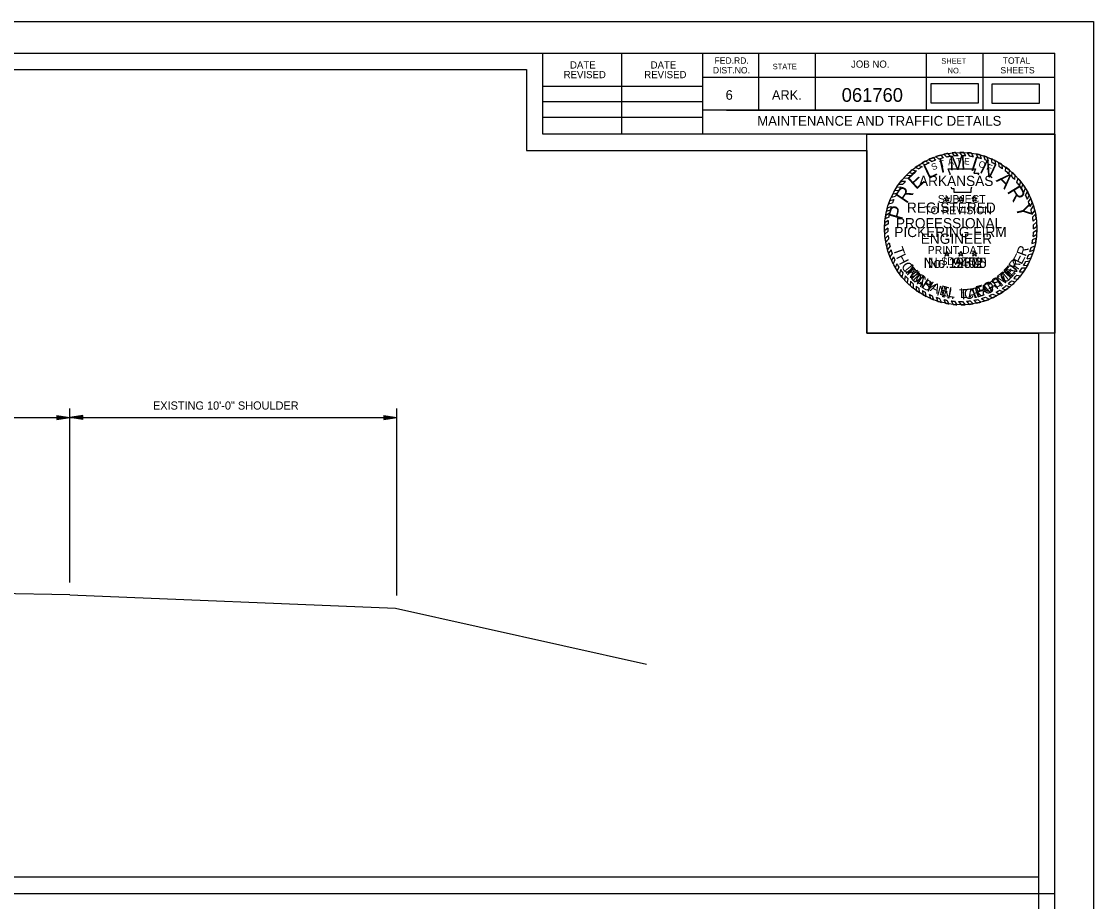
# Model space of a CAD drawing. Extents: x -500 to 213, y 382723 to 382830.
# Drawn here: x 147.8 to 213.4, y 382776 to 382829.8 of the extents above; entities that cross this region are included whole.
import ezdxf

# ---------------------------------------------------------------- set-up
doc = ezdxf.new("R2010")
doc.units = 0
for name, color, linetype in [('Default', 7, 'Continuous'), ('R_Border', 7, 'Continuous'), ('R_Border Notes', 7, 'Continuous'), ('R_Border Plan-Plan', 7, 'Continuous'), ('R_No Plot', 7, 'Continuous'), ('STAMP_PE_CRAFTON', 7, 'Continuous'), ('STAMP_PE_FOSTER', 7, 'Continuous'), ('STAMP_PE_SEAL-INFO', 7, 'Continuous'), ('STAMP_PE_TAEGTMEYER', 7, 'Continuous'), ('STAMP_PE_TXT', 7, 'Continuous'), ('STAMP_PRELIMINARY', 7, 'Continuous')]:
    doc.layers.add(name, color=color, linetype=linetype)

msp = doc.modelspace()

# ---------------------------------------------------------------- linework, layer by layer
at = {"layer": 'Default'}
for p, q in [((150.803, 382804.615), (150.803, 382806.125)), ((170.807, 382804.767), (170.807, 382806.125)), ((126.798, 382805.575), (150.803, 382805.575)), ((150.003, 382805.695), (150.803, 382805.575)), ((150.003, 382805.695), (150.003, 382805.455)), ((150.003, 382805.675), (150.669, 382805.575)), ((150.003, 382805.655), (150.531, 382805.575)), ((150.003, 382805.635), (150.399, 382805.575)), ((150.003, 382805.615), (150.263, 382805.575)), ((150.003, 382805.595), (150.129, 382805.575)), ((150.003, 382805.455), (150.803, 382805.575)), ((150.003, 382805.537), (150.263, 382805.575)), ((150.003, 382805.495), (150.531, 382805.575)), ((150.003, 382805.475), (150.669, 382805.575)), ((150.003, 382805.515), (150.399, 382805.575)), ((150.003, 382805.557), (150.129, 382805.575)), ((151.603, 382805.695), (150.803, 382805.575)), ((150.803, 382805.575), (170.807, 382805.575)), ((151.603, 382805.455), (150.803, 382805.575)), ((151.603, 382805.675), (150.937, 382805.575)), ((151.603, 382805.475), (150.937, 382805.575)), ((151.603, 382805.655), (151.075, 382805.575)), ((151.603, 382805.495), (151.075, 382805.575)), ((151.603, 382805.635), (151.207, 382805.575)), ((151.603, 382805.515), (151.207, 382805.575)), ((151.603, 382805.615), (151.343, 382805.575)), ((151.603, 382805.537), (151.343, 382805.575)), ((151.603, 382805.595), (151.477, 382805.575)), ((151.603, 382805.557), (151.477, 382805.575)), ((151.603, 382805.455), (151.603, 382805.695)), ((170.007, 382805.695), (170.807, 382805.575)), ((170.007, 382805.695), (170.007, 382805.455)), ((170.007, 382805.675), (170.673, 382805.575)), ((170.007, 382805.655), (170.535, 382805.575)), ((170.007, 382805.635), (170.403, 382805.575)), ((170.007, 382805.615), (170.267, 382805.575)), ((170.007, 382805.595), (170.133, 382805.575)), ((170.007, 382805.455), (170.807, 382805.575)), ((170.007, 382805.537), (170.267, 382805.575)), ((170.007, 382805.495), (170.535, 382805.575)), ((170.007, 382805.475), (170.673, 382805.575)), ((170.007, 382805.515), (170.403, 382805.575)), ((170.007, 382805.557), (170.133, 382805.575)), ((150.803, 382795.489), (150.803, 382804.615)), ((170.807, 382794.691), (170.807, 382804.767)), ((150.803, 382794.729), (126.798, 382795.209)), ((150.803, 382794.729), (170.731, 382793.933)), ((170.731, 382793.933), (186.09, 382790.492))]:
    msp.add_line(p, q, dxfattribs=at)
for points in [[(203.479, 382824.821), (206.395, 382824.821), (206.395, 382825.976), (203.479, 382825.976)], [(207.217, 382824.804), (210.134, 382824.804), (210.134, 382825.959), (207.217, 382825.959)]]:
    msp.add_lwpolyline(points, close=True, dxfattribs=at)
at = {"layer": 'R_Border'}
for p, q in [((52.967, 382827.85), (211.057, 382827.85)), ((179.737, 382822.91), (179.737, 382827.85)), ((184.577, 382822.91), (184.577, 382827.85)), ((189.507, 382827.85), (189.507, 382822.91)), ((192.927, 382827.85), (192.927, 382824.38)), ((196.397, 382827.85), (196.397, 382824.38)), ((203.187, 382827.85), (203.187, 382824.38)), ((206.657, 382827.85), (206.657, 382824.38)), ((211.057, 382725.12), (211.057, 382827.85)), ((211.057, 382826.38), (189.507, 382826.38)), ((211.057, 382826.39), (211.057, 382826.39)), ((179.737, 382825.84), (189.507, 382825.84)), ((179.737, 382824.91), (189.507, 382824.91)), ((211.057, 382824.38), (189.507, 382824.38)), ((190.987, 382824.38), (211.057, 382824.38)), ((179.737, 382823.94), (189.507, 382823.94)), ((211.057, 382822.91), (179.737, 382822.91))]:
    msp.add_line(p, q, dxfattribs=at)
at = {"layer": 'R_Border Plan-Plan'}
msp.add_line((52.967, 382776.485), (211.057, 382776.485), dxfattribs=at)
at = {"layer": 'R_No Plot'}
for points in [[(46.763, 382829.798), (213.433, 382829.798), (213.433, 382723.129), (46.763, 382723.129)], [(210.057, 382777.485), (53.967, 382777.485), (53.967, 382826.85), (178.737, 382826.85), (178.737, 382821.91), (187.507, 382821.91), (199.557, 382821.91), (199.557, 382810.744), (210.057, 382810.744)], [(53.967, 382826.85), (178.737, 382826.85), (178.737, 382821.91), (187.507, 382821.91), (199.557, 382821.91), (199.557, 382810.744), (210.057, 382810.744), (210.057, 382726.12), (53.967, 382726.12)], [(199.557, 382822.91), (211.057, 382822.91), (211.057, 382810.744), (199.557, 382810.744)]]:
    msp.add_lwpolyline(points, close=True, dxfattribs=at)
at = {"layer": 'STAMP_PE_SEAL-INFO'}
for p, q in [((204.082, 382821.629), (204.226, 382821.455)), ((204.276, 382821.678), (204.454, 382821.506)), ((204.517, 382821.726), (204.667, 382821.542)), ((204.775, 382821.763), (204.915, 382821.571)), ((205.143, 382821.585), (204.987, 382821.782)), ((205.392, 382821.588), (205.252, 382821.793)), ((205.621, 382821.577), (205.491, 382821.789)), ((205.873, 382821.552), (205.727, 382821.774)), ((206.086, 382821.52), (205.958, 382821.747)), ((206.367, 382821.46), (206.28, 382821.69)), ((206.568, 382821.406), (206.489, 382821.641)), ((206.794, 382821.333), (206.723, 382821.573)), ((202.726, 382821.013), (202.947, 382820.912)), ((202.919, 382821.135), (203.135, 382821.024)), ((203.143, 382821.261), (203.375, 382821.148)), ((203.359, 382821.366), (203.553, 382821.229)), ((203.613, 382821.474), (203.76, 382821.311)), ((203.786, 382821.538), (203.977, 382821.385)), ((207.003, 382821.253), (206.931, 382821.501)), ((207.234, 382821.15), (207.183, 382821.399)), ((207.457, 382821.036), (207.413, 382821.29)), ((207.651, 382820.922), (207.631, 382821.172)), ((207.868, 382820.779), (207.852, 382821.037)), ((201.988, 382820.405), (202.26, 382820.384)), ((202.155, 382820.566), (202.385, 382820.497)), ((202.327, 382820.716), (202.592, 382820.666)), ((202.516, 382820.88), (202.743, 382820.778)), ((204.543, 382820.777), (206.215, 382820.777)), ((204.604, 382820.624), (204.543, 382820.777)), ((204.656, 382820.475), (204.604, 382820.624)), ((204.659, 382820.418), (204.656, 382820.475)), ((206.215, 382820.777), (206.103, 382820.531)), ((206.103, 382820.531), (206.419, 382820.531)), ((206.419, 382820.531), (206.347, 382820.418)), ((208.048, 382820.646), (208.065, 382820.889)), ((208.271, 382820.459), (208.281, 382820.721)), ((208.428, 382820.313), (208.462, 382820.563)), ((208.607, 382820.127), (208.641, 382820.39)), ((201.397, 382819.67), (201.655, 382819.687)), ((201.514, 382819.842), (201.767, 382819.839)), ((201.653, 382820.027), (201.928, 382820.038)), ((201.826, 382820.232), (202.087, 382820.213)), ((204.755, 382819.563), (204.742, 382819.672)), ((205.974, 382819.672), (205.935, 382819.517)), ((208.744, 382819.968), (208.812, 382820.204)), ((208.906, 382819.76), (208.974, 382820.01)), ((209.016, 382819.602), (209.105, 382819.834)), ((209.17, 382819.354), (209.261, 382819.599)), ((201.064, 382819.063), (201.316, 382819.115)), ((201.158, 382819.258), (201.408, 382819.29)), ((201.274, 382819.469), (201.519, 382819.48)), ((204.912, 382819.563), (204.755, 382819.563)), ((204.912, 382819.348), (204.912, 382819.563)), ((205.927, 382819.348), (204.912, 382819.348)), ((205.935, 382819.517), (205.927, 382819.348)), ((209.27, 382819.17), (209.383, 382819.392)), ((209.385, 382818.928), (209.498, 382819.171)), ((209.456, 382818.76), (209.587, 382818.977)), ((200.767, 382818.189), (201.002, 382818.285)), ((200.819, 382818.393), (201.058, 382818.477)), ((200.897, 382818.644), (201.14, 382818.712)), ((200.972, 382818.847), (201.225, 382818.92)), ((209.553, 382818.485), (209.688, 382818.722)), ((209.607, 382818.303), (209.754, 382818.529)), ((200.906, 382817.836), (200.683, 382817.725)), ((200.949, 382818.066), (200.716, 382817.941)), ((209.673, 382818.024), (209.833, 382818.247)), ((209.708, 382817.834), (209.885, 382818.01)), ((209.741, 382817.579), (209.927, 382817.747)), ((200.858, 382817.406), (200.648, 382817.278)), ((200.85, 382817.159), (200.648, 382816.991)), ((200.877, 382817.618), (200.658, 382817.478)), ((209.757, 382817.37), (209.952, 382817.516)), ((209.758, 382816.908), (209.967, 382817.047)), ((209.763, 382817.111), (209.966, 382817.272)), ((200.853, 382816.956), (200.658, 382816.793)), ((200.87, 382816.708), (200.684, 382816.53)), ((200.896, 382816.493), (200.719, 382816.307)), ((209.713, 382816.461), (209.934, 382816.571)), ((209.738, 382816.655), (209.955, 382816.783)), ((200.935, 382816.264), (200.766, 382816.08)), ((200.982, 382816.055), (200.826, 382815.847)), ((201.044, 382815.831), (200.897, 382815.622)), ((209.54, 382815.738), (209.785, 382815.838)), ((209.613, 382815.985), (209.849, 382816.086)), ((209.667, 382816.211), (209.895, 382816.309)), ((201.114, 382815.619), (200.974, 382815.414)), ((201.198, 382815.406), (201.067, 382815.195)), ((201.283, 382815.214), (201.17, 382814.984)), ((209.285, 382815.123), (209.529, 382815.157)), ((209.366, 382815.291), (209.61, 382815.339)), ((209.473, 382815.548), (209.714, 382815.614)), ((201.401, 382814.985), (201.305, 382814.74)), ((201.519, 382814.784), (201.427, 382814.548)), ((201.62, 382814.628), (201.565, 382814.352)), ((201.76, 382814.433), (201.709, 382814.167)), ((208.893, 382814.486), (209.146, 382814.488)), ((209.063, 382814.733), (209.302, 382814.73)), ((209.149, 382814.873), (209.399, 382814.901)), ((201.912, 382814.244), (201.869, 382813.984)), ((202.064, 382814.075), (202.033, 382813.814)), ((202.225, 382813.912), (202.21, 382813.648)), ((202.397, 382813.756), (202.395, 382813.491)), ((208.217, 382813.757), (208.453, 382813.692)), ((208.42, 382813.943), (208.641, 382813.874)), ((208.548, 382814.073), (208.786, 382814.03)), ((208.739, 382814.289), (208.97, 382814.249)), ((202.577, 382813.609), (202.586, 382813.347)), ((202.746, 382813.484), (202.764, 382813.225)), ((202.96, 382813.343), (202.99, 382813.087)), ((203.135, 382813.24), (203.18, 382812.984)), ((203.375, 382813.115), (203.454, 382812.855)), ((207.269, 382813.13), (207.511, 382813.024)), ((207.473, 382813.237), (207.681, 382813.12)), ((207.68, 382813.359), (207.905, 382813.261)), ((207.852, 382813.473), (208.071, 382813.378)), ((208.082, 382813.645), (208.316, 382813.572)), ((203.562, 382813.031), (203.648, 382812.775)), ((203.808, 382812.935), (203.913, 382812.684)), ((204.013, 382812.867), (204.126, 382812.622)), ((204.267, 382812.798), (204.373, 382812.565)), ((204.465, 382812.755), (204.589, 382812.526)), ((204.716, 382812.714), (204.836, 382812.494)), ((204.934, 382812.691), (205.071, 382812.476)), ((205.176, 382812.677), (205.327, 382812.47)), ((205.406, 382812.676), (205.578, 382812.478)), ((205.665, 382812.689), (205.828, 382812.5)), ((205.884, 382812.713), (206.071, 382812.533)), ((206.107, 382812.747), (206.301, 382812.578)), ((206.353, 382812.8), (206.542, 382812.637)), ((206.583, 382812.862), (206.791, 382812.713)), ((206.829, 382812.943), (207.051, 382812.809)), ((207.039, 382813.025), (207.251, 382812.895))]:
    msp.add_line(p, q, dxfattribs=at)
for radius, start, end in [(4.661, 105.23389, 109.03519), (4.661, 99.75254, 102.77648), (4.661, 93.93815, 96.55172), (4.457, 92.11016, 95.03666), (4.661, 87.72979, 90.67067), (4.457, 85.96279, 88.9097), (4.661, 81.97315, 84.82355), (4.661, 75.31251, 77.94263), (4.661, 69.60611, 72.30577), (4.661, 123.61993, 126.59063), (4.457, 121.97456, 125.11001), (4.661, 117.65441, 120.80988), (4.457, 115.68692, 119.15827), (4.661, 111.31242, 114.70259), (4.457, 110.30864, 113.16588), (4.457, 104.03521, 107.36155), (4.457, 98.25799, 101.03289), (4.457, 79.92642, 82.69597), (4.457, 73.55748, 76.23144), (4.457, 67.62483, 70.50398), (4.661, 63.13288, 66.2704), (4.457, 61.15575, 64.37837), (4.661, 56.90029, 60.09423), (4.457, 54.92383, 58.27016), (4.661, 135.40208, 138.30314), (4.457, 133.13306, 136.25623), (4.661, 129.73259, 132.53764), (4.457, 127.52969, 130.96829), (4.457, 48.30163, 52.03953), (4.661, 50.3492, 53.71593), (4.457, 42.22116, 45.55119), (4.661, 44.3405, 47.39292), (4.661, 147.00719, 149.89904), (4.661, 141.60556, 144.44865), (4.457, 145.01972, 148.21036), (4.457, 139.30101, 142.58729), (4.457, 36.13503, 39.53106), (4.661, 38.12472, 41.23157), (4.457, 29.90321, 33.66454), (4.661, 31.96138, 35.42937), (4.661, 152.86398, 155.51889), (4.457, 151.03153, 153.57304), (4.457, 23.77322, 27.22114), (4.661, 25.93909, 29.01247), (4.661, 19.95381, 23.31409), (4.661, 164.3068, 166.89395), (4.661, 158.40766, 161.07015), (4.457, 162.43309, 165.00133), (4.457, 156.34018, 159.23194), (4.457, 17.68022, 21.42509), (4.457, 11.54445, 15.23639), (4.661, 13.84205, 17.44468), (4.661, 170.0003, 172.68778), (4.457, 167.90481, 170.90393), (4.457, 5.7599, 9.06056), (4.661, 7.58519, 10.86211), (4.661, 175.74093, 178.2066), (4.661, 181.72508, 184.16255), (4.457, 179.64537, 182.26333), (4.457, 173.73, 176.47337), (4.457, 359.73289, 3.06392), (4.661, 1.72155, 4.72681), (4.661, 355.71562, 358.95694), (4.661, 187.42037, 190.19271), (4.457, 185.45389, 188.23401), (4.457, 348.07782, 351.34355), (4.457, 353.86319, 357.12742), (4.661, 349.83047, 353.08845), (4.661, 193.03695, 195.99732), (4.457, 191.22736, 193.98583), (4.457, 196.96751, 199.83526), (4.457, 341.77699, 345.09248), (4.661, 343.89247, 347.03502), (4.661, 198.89671, 201.62812), (4.661, 204.54793, 207.43282), (4.457, 202.77613, 205.47915), (4.457, 329.55488, 333.20757), (4.457, 335.6038, 339.18578), (4.661, 331.40371, 334.93315), (4.661, 337.38367, 340.99332), (4.661, 210.86355, 213.65709), (4.457, 208.78826, 211.79343), (4.661, 216.61154, 219.49098), (4.457, 214.18375, 217.27474), (4.457, 323.58513, 327.44069), (4.661, 325.44052, 328.98725), (4.661, 222.47995, 225.38008), (4.457, 220.39088, 223.30564), (4.457, 226.24938, 229.24068), (4.457, 310.77436, 314.31605), (4.661, 312.45177, 315.66328), (4.457, 316.65308, 320.37109), (4.661, 318.28455, 321.80429), (4.661, 228.36648, 231.34802), (4.457, 232.22904, 234.93361), (4.661, 234.29502, 236.94517), (4.457, 238.22227, 240.83529), (4.661, 240.1977, 242.86128), (4.457, 244.32043, 246.94859), (4.457, 292.87452, 296.11851), (4.457, 299.07679, 302.17235), (4.661, 300.62101, 303.87026), (4.457, 304.82299, 308.51428), (4.661, 306.37206, 310.20799), (4.661, 246.57598, 249.15579), (4.457, 250.34912, 253.12157), (4.661, 252.59667, 255.32518), (4.457, 256.50505, 259.11916), (4.661, 258.44328, 261.13983), (4.457, 262.37828, 265.20115), (4.661, 264.19784, 267.10092), (4.457, 268.3215, 271.27698), (4.661, 270.25484, 273.33609), (4.457, 274.61565, 277.44863), (4.661, 276.42389, 279.43574), (4.457, 280.34588, 283.58137), (4.661, 282.31994, 285.37019), (4.457, 286.64233, 289.97826), (4.661, 288.57086, 291.97334), (4.661, 294.64808, 298.21662)]:
    msp.add_arc((205.307, 382817.132), radius, start, end, dxfattribs=at)
at = {"layer": 'STAMP_PE_TXT'}
for p, q in [((204.396, 382818.917), (204.297, 382818.99)), ((204.297, 382818.99), (204.42, 382818.99)), ((204.42, 382818.99), (204.458, 382819.106)), ((204.458, 382819.106), (204.496, 382818.99)), ((204.496, 382818.99), (204.618, 382818.99)), ((204.618, 382818.99), (204.519, 382818.917)), ((205.245, 382818.917), (205.146, 382818.99)), ((205.146, 382818.99), (205.269, 382818.99)), ((205.269, 382818.99), (205.307, 382819.106)), ((205.307, 382819.106), (205.345, 382818.99)), ((205.345, 382818.99), (205.467, 382818.99)), ((205.467, 382818.99), (205.368, 382818.917)), ((206.094, 382818.917), (205.995, 382818.99)), ((205.995, 382818.99), (206.118, 382818.99)), ((206.118, 382818.99), (206.156, 382819.106)), ((206.156, 382819.106), (206.194, 382818.99)), ((206.194, 382818.99), (206.316, 382818.99)), ((206.316, 382818.99), (206.217, 382818.917)), ((204.359, 382818.801), (204.396, 382818.917)), ((204.458, 382818.873), (204.359, 382818.801)), ((204.557, 382818.801), (204.458, 382818.873)), ((204.519, 382818.917), (204.557, 382818.801)), ((205.208, 382818.801), (205.245, 382818.917)), ((205.307, 382818.873), (205.208, 382818.801)), ((205.406, 382818.801), (205.307, 382818.873)), ((205.368, 382818.917), (205.406, 382818.801)), ((206.057, 382818.801), (206.094, 382818.917)), ((206.156, 382818.873), (206.057, 382818.801)), ((206.255, 382818.801), (206.156, 382818.873)), ((206.217, 382818.917), (206.255, 382818.801)), ((204.42, 382815.636), (204.458, 382815.753)), ((204.458, 382815.753), (204.496, 382815.636)), ((205.269, 382815.636), (205.307, 382815.753)), ((205.307, 382815.753), (205.345, 382815.636)), ((206.118, 382815.636), (206.156, 382815.753)), ((206.156, 382815.753), (206.194, 382815.636)), ((204.396, 382815.564), (204.297, 382815.636)), ((204.297, 382815.636), (204.42, 382815.636)), ((204.359, 382815.447), (204.396, 382815.564)), ((204.458, 382815.519), (204.359, 382815.447)), ((204.557, 382815.447), (204.458, 382815.519)), ((204.496, 382815.636), (204.618, 382815.636)), ((204.618, 382815.636), (204.519, 382815.564)), ((204.519, 382815.564), (204.557, 382815.447)), ((205.245, 382815.564), (205.146, 382815.636)), ((205.146, 382815.636), (205.269, 382815.636)), ((205.208, 382815.447), (205.245, 382815.564)), ((205.307, 382815.519), (205.208, 382815.447)), ((205.406, 382815.447), (205.307, 382815.519)), ((205.345, 382815.636), (205.467, 382815.636)), ((205.467, 382815.636), (205.368, 382815.564)), ((205.368, 382815.564), (205.406, 382815.447)), ((206.094, 382815.564), (205.995, 382815.636)), ((205.995, 382815.636), (206.118, 382815.636)), ((206.057, 382815.447), (206.094, 382815.564)), ((206.156, 382815.519), (206.057, 382815.447)), ((206.255, 382815.447), (206.156, 382815.519)), ((206.194, 382815.636), (206.316, 382815.636)), ((206.316, 382815.636), (206.217, 382815.564)), ((206.217, 382815.564), (206.255, 382815.447))]:
    msp.add_line(p, q, dxfattribs=at)
at = {"layer": 'STAMP_PRELIMINARY'}
msp.add_circle((205.307, 382817.132), 4.661, dxfattribs=at)

# ---------------------------------------------------------------- texts
at = {"layer": 'Default'}
msp.add_text('EXISTING 10\'-0" SHOULDER', height=0.5001, dxfattribs=at).set_placement((155.892, 382806.064))
at = {"layer": 'R_Border'}
for s, height, p in [('FED.RD.', 0.391, (190.247, 382827.21)), ('SHEET', 0.342, (204.117, 382827.21)), ('TOTAL', 0.391, (207.877, 382827.21)), ('DATE', 0.4396, (181.406, 382826.919)), ('DATE', 0.4396, (186.336, 382826.919)), ('DIST.NO.', 0.391, (190.147, 382826.62)), ('STATE', 0.342, (193.807, 382826.87)), ('JOB NO.', 0.4396, (198.597, 382826.97)), ('NO.', 0.342, (204.507, 382826.62)), ('SHEETS', 0.391, (207.737, 382826.62)), ('REVISED', 0.4396, (181.016, 382826.329)), ('REVISED', 0.4396, (185.946, 382826.329)), ('6', 0.586, (190.927, 382825.01)), ('ARK.', 0.5861, (193.757, 382825.01))]:
    msp.add_text(s, height=height, dxfattribs=at).set_placement(p)
at = {"layer": 'R_Border Notes'}
for s, height, p in [('061760', 0.84, (198.025, 382824.883)), ('MAINTENANCE AND TRAFFIC DETAILS', 0.6, (192.86, 382823.42))]:
    msp.add_text(s, height=height, dxfattribs=at).set_placement(p)
at = {"layer": 'STAMP_PE_CRAFTON'}
msp.add_text('No. 12370', height=0.625, dxfattribs=at).set_placement((203.038, 382814.73))
for s, rotation, p in [('T', 310.74416, (201.79, 382814.581)), ('O', 317.64216, (202.123, 382814.175)), ('O', 41.83906, (208.024, 382813.752)), ('N', 49.24107, (208.448, 382814.143)), ('N', 324.45371, (202.546, 382813.783)), ('Y', 331.16864, (203.063, 382813.424)), ('A', 20.51248, (206.647, 382813.01)), ('F', 28.78207, (207.137, 382813.196)), ('T', 34.11362, (207.595, 382813.451)), ('N', 347.47515, (204.09, 382812.966)), ('C', 6.01169, (205.542, 382812.802)), ('R', 14.81888, (206.091, 382812.86)), ('.', 356.89262, (204.705, 382812.828))]:
    msp.add_text(s, height=0.625, rotation=rotation, dxfattribs=at).set_placement(p)
at = {"layer": 'STAMP_PE_FOSTER'}
msp.add_text('No. 9402', height=0.625, dxfattribs=at).set_placement((203.3, 382814.73))
for s, rotation, p in [('R', 54.5031, (208.669, 382814.537)), ('M', 308.33902, (201.865, 382814.643)), ('I', 314.18423, (202.264, 382814.174)), ('C', 319.87327, (202.441, 382813.997)), ('T', 39.41938, (207.878, 382813.752)), ('E', 46.96131, (208.307, 382814.127)), ('H', 327.72349, (202.905, 382813.629)), ('A', 335.72761, (203.396, 382813.338)), ('F', 15.86908, (206.324, 382813.009)), ('O', 23.71897, (206.846, 382813.173)), ('S', 31.72336, (207.402, 382813.438)), ('E', 343.5779, (203.964, 382813.103)), ('L', 350.81148, (204.494, 382812.964)), ('L', 1.26658, (205.263, 382812.886)), ('.', 6.80354, (205.787, 382812.915))]:
    msp.add_text(s, height=0.6, rotation=rotation, dxfattribs=at).set_placement(p)
at = {"layer": 'STAMP_PE_TAEGTMEYER'}
for s, rotation, p in [('T', 289.64597, (201.154, 382815.887)), ('R', 69.57001, (209.279, 382815.389)), ('H', 296.73386, (201.334, 382815.395)), ('O', 303.77078, (201.63, 382814.841)), ('Y', 53.99864, (208.695, 382814.428)), ('E', 63.0984, (209.03, 382814.898)), ('M', 314.20329, (201.958, 382814.365)), ('M', 39.30005, (207.806, 382813.581)), ('E', 46.80938, (208.326, 382814.02)), ('A', 321.0594, (202.439, 382813.883)), ('S', 327.82385, (202.852, 382813.561)), ('G', 23.30524, (206.807, 382813.063)), ('T', 31.46601, (207.357, 382813.309)), ('N', 344.27273, (203.8, 382813.058)), ('T', 3.00609, (205.239, 382812.792)), ('A', 8.98261, (205.762, 382812.82)), ('E', 17.68363, (206.282, 382812.897)), ('.', 350.64643, (204.406, 382812.892))]:
    msp.add_text(s, height=0.625, rotation=rotation, dxfattribs=at).set_placement(p)
msp.add_text('No. 19605', height=0.625, dxfattribs=at).set_placement((203.038, 382814.73))
at = {"layer": 'STAMP_PE_TXT'}
for s, rotation, p in [('S', 23.5541, (203.606, 382820.684)), ('T', 16.311, (204.068, 382820.87)), ('A', 9.0679, (204.549, 382820.996)), ('T', 1.82479, (205.042, 382821.061)), ('E', 355.20019, (205.497, 382821.065)), ('O', 342.25065, (206.36, 382820.927)), ('F', 335.00755, (206.843, 382820.758))]:
    msp.add_text(s, height=0.391, rotation=rotation, dxfattribs=at).set_placement(p)
for s, p in [('ARKANSAS', (202.753, 382819.737)), ('REGISTERED', (202.015, 382818.102)), ('PROFESSIONAL', (201.341, 382817.151)), ('ENGINEER', (202.861, 382816.201))]:
    msp.add_text(s, height=0.625, dxfattribs=at).set_placement(p)
at = {"layer": 'STAMP_PRELIMINARY'}
for s, rotation, p in [('M', 3.10738, (204.625, 382820.68)), ('L', 25.51305, (203.311, 382820.145)), ('I', 12.52485, (204.076, 382820.525)), ('I', 342.31637, (205.858, 382820.713)), ('N', 333.9382, (206.412, 382820.576)), ('E', 42.35784, (202.57, 382819.48)), ('A', 315.65789, (207.429, 382820.064)), ('R', 56.22922, (201.992, 382818.614)), ('R', 301.38306, (208.113, 382819.407)), ('P', 73.91301, (201.717, 382817.602)), ('Y', 283.25926, (208.658, 382818.513))]:
    msp.add_text(s, height=0.9, rotation=rotation, dxfattribs=at).set_placement(p)
for s, height, p in [('SUBJECT', 0.48, (203.907, 382818.706)), ('TO REVISION', 0.48, (203.074, 382818.014)), ('PICKERING FIRM', 0.625, (201.243, 382816.613)), ('PRINT DATE', 0.48, (203.285, 382815.589)), ('$DATE$', 0.48, (204.124, 382814.897))]:
    msp.add_text(s, height=height, dxfattribs=at).set_placement(p)

doc.saveas('drawing.dxf')
